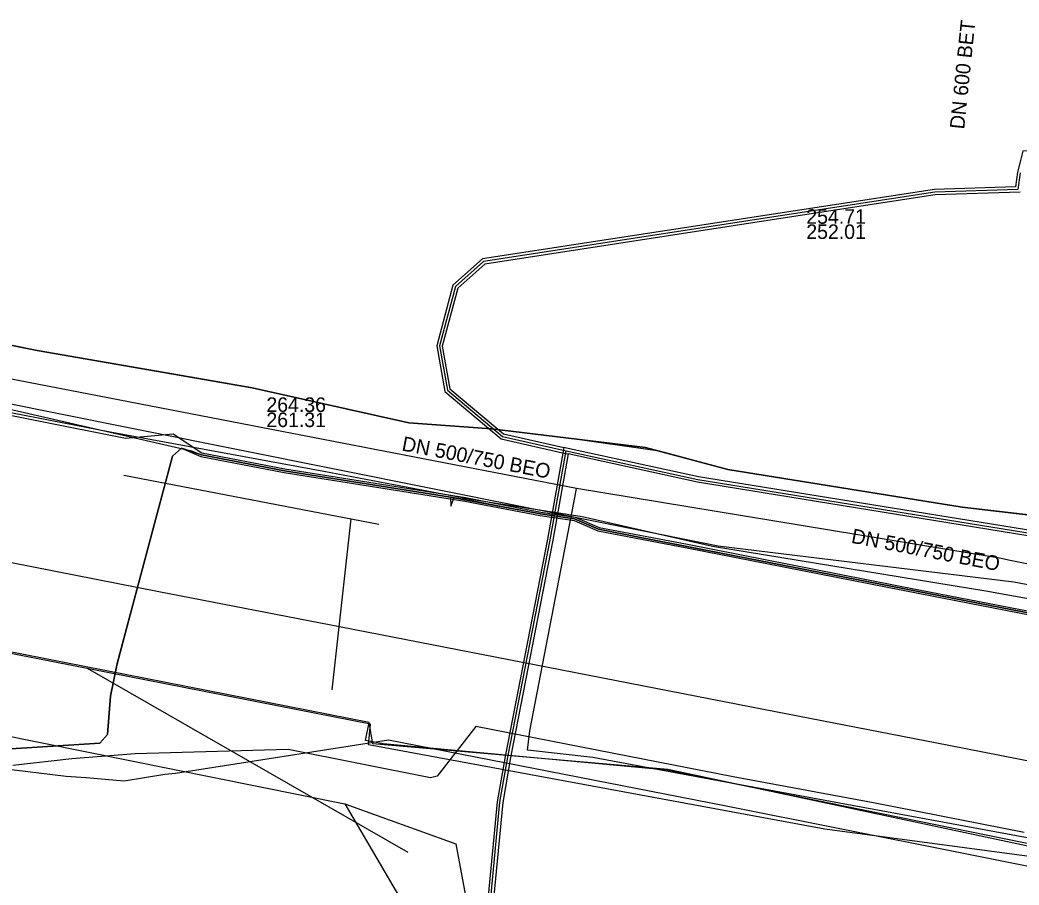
# Model space of a CAD drawing. Extents: x -599951 to -598963, y -1164095 to -1162939.
# Drawn here: x -599878 to -599823.1, y -1163059.7 to -1163012.2 of the extents above; entities that cross this region are included whole.
import ezdxf

# ---------------------------------------------------------------- set-up
doc = ezdxf.new("R2010")
doc.units = 0
for name, color, linetype in [('Vrstva 12', 7, 'Continuous'), ('Vrstva 19', 7, 'Continuous'), ('Vrstva 20', 7, 'Continuous'), ('Vrstva 42', 7, 'Continuous'), ('Vrstva 44', 7, 'Continuous'), ('Vrstva 50', 7, 'Continuous'), ('Vrstva 55', 7, 'Continuous'), ('Vrstva 58', 7, 'Continuous'), ('Vrstva 9', 7, 'Continuous')]:
    doc.layers.add(name, color=color, linetype=linetype)

msp = doc.modelspace()

# ---------------------------------------------------------------- linework, layer by layer
at = {"layer": 'Vrstva 12'}
for p, q in [((-599847.38, -1163037.95), (-599925.54, -1163022.8)), ((-599824.16, -1163041.78), (-599847.38, -1163037.95)), ((-599823.57, -1163041.9), (-599824.16, -1163041.78)), ((-599821.8, -1163042.25), (-599823.57, -1163041.9)), ((-599882.67, -1163050.72), (-599860.12, -1163055.28))]:
    msp.add_line(p, q, dxfattribs=at)
for points in [[(-599846.49, -1163052.73), (-599850.07, -1163052.32), (-599849.95, -1163051.27), (-599847.53, -1163038.73), (-599847.38, -1163037.95)], [(-599808.4, -1163075.41), (-599806.05, -1163063.47), (-599805.96, -1163062.96), (-599805.85, -1163062.25), (-599805.95, -1163061.63), (-599806.18, -1163061.15), (-599806.36, -1163060.78), (-599806.57, -1163060.51), (-599807.02, -1163060.09), (-599808.54, -1163059.75), (-599841.96, -1163053.57), (-599846.49, -1163052.73)], [(-599860.12, -1163055.28), (-599854.02, -1163057.48), (-599852.65, -1163064.87), (-599821.22, -1163071.4), (-599813.284, -1163073.958)], [(-599860.12, -1163055.28), (-599856.6, -1163061.29), (-599853.92, -1163067.61), (-599829.07, -1163071.62), (-599820.67, -1163074.02), (-599813.582, -1163075.481)]]:
    msp.add_lwpolyline(points, dxfattribs=at)
at = {"layer": 'Vrstva 19'}
for points in [[(-599875.409, -1163053.774), (-599879.03, -1163053.341), (-599951.125, -1163042.261)], [(-599741.561, -1163083.741), (-599749.337, -1163082.368), (-599759.986, -1163080.568), (-599773.585, -1163078.162), (-599785.969, -1163075.634), (-599789.812, -1163076.062), (-599794.62, -1163074.71), (-599796.63, -1163073), (-599800.62, -1163069), (-599804.87, -1163064.7), (-599807.8, -1163061.67), (-599826.41, -1163057.95), (-599839.25, -1163055.38), (-599857.71, -1163051.77), (-599869.416, -1163053.613), (-599869.995, -1163053.663), (-599872.225, -1163054.024), (-599874.316, -1163053.849), (-599875.409, -1163053.774)]]:
    msp.add_lwpolyline(points, dxfattribs=at)
at = {"layer": 'Vrstva 20'}
msp.add_lwpolyline([(-599883.05, -1163052.54), (-599873.56, -1163051.94), (-599873.14, -1163051.47), (-599872.98, -1163049.36), (-599872.6, -1163047.57), (-599869.57, -1163036.17), (-599869.08, -1163035.73), (-599867.99, -1163036.09), (-599863.42, -1163036.97), (-599853.5, -1163038.54), (-599849.37, -1163039.34), (-599847.49, -1163039.61), (-599846.18, -1163040.18), (-599841.31, -1163041.11), (-599828.6, -1163043.61), (-599815.43, -1163046.17), (-599809.1, -1163047.15), (-599803.22, -1163048.59), (-599792.42, -1163050.98), (-599783.94, -1163051.78), (-599774.84, -1163053.7), (-599762.66, -1163055.93), (-599749, -1163058.61), (-599740.93, -1163058.73)], dxfattribs=at)
at = {"layer": 'Vrstva 42'}
for p, q in [((-599895.104, -1163026.704), (-599877.002, -1163030.363)), ((-599895.104, -1163026.704), (-599877.002, -1163030.363)), ((-599877.002, -1163030.363), (-599865.209, -1163032.412)), ((-599877.002, -1163030.363), (-599865.209, -1163032.412)), ((-599865.209, -1163032.412), (-599856.59, -1163034.344)), ((-599865.209, -1163032.412), (-599856.59, -1163034.344)), ((-599856.59, -1163034.344), (-599852.059, -1163034.673)), ((-599856.59, -1163034.344), (-599852.059, -1163034.673)), ((-599852.059, -1163034.673), (-599843.593, -1163035.7)), ((-599852.059, -1163034.673), (-599843.593, -1163035.7)), ((-599843.593, -1163035.7), (-599839.077, -1163036.896)), ((-599843.593, -1163035.7), (-599839.077, -1163036.896)), ((-599839.077, -1163036.896), (-599826.206, -1163038.978)), ((-599839.077, -1163036.896), (-599826.206, -1163038.978)), ((-599826.206, -1163038.978), (-599807.734, -1163041.119)), ((-599826.206, -1163038.978), (-599807.734, -1163041.119))]:
    msp.add_line(p, q, dxfattribs=at)
for points in [[(-599815.518, -1163019.48), (-599820.791, -1163019.23), (-599821.01, -1163019.37), (-599822.87, -1163019.4), (-599823.02, -1163019.991), (-599823.159, -1163020.568), (-599823.271, -1163021.364), (-599827.714, -1163021.51), (-599835.493, -1163022.702), (-599852.557, -1163025.328), (-599854.173, -1163026.768), (-599855.063, -1163030.103), (-599854.618, -1163032.62), (-599851.529, -1163035.218), (-599847.993, -1163036.016), (-599847.84, -1163036.05), (-599848.693, -1163040.788), (-599851.012, -1163052.737), (-599851.441, -1163055.21), (-599851.947, -1163060.521), (-599893.107, -1163090.941)], [(-599815.518, -1163019.48), (-599820.791, -1163019.23), (-599821.01, -1163019.37), (-599822.87, -1163019.4), (-599823.02, -1163019.991), (-599823.159, -1163020.568), (-599823.271, -1163021.364), (-599827.714, -1163021.51), (-599835.493, -1163022.702), (-599852.557, -1163025.328), (-599854.173, -1163026.768), (-599855.063, -1163030.103), (-599854.618, -1163032.62), (-599851.529, -1163035.218), (-599847.993, -1163036.016), (-599847.84, -1163036.05), (-599848.693, -1163040.788), (-599851.012, -1163052.737), (-599851.441, -1163055.21), (-599851.947, -1163060.521), (-599893.107, -1163090.941)], [(-599823.02, -1163019.991), (-599823.159, -1163020.568), (-599823.271, -1163021.364), (-599827.714, -1163021.51), (-599835.493, -1163022.702), (-599852.557, -1163025.328), (-599854.173, -1163026.768), (-599855.063, -1163030.103), (-599854.618, -1163032.62), (-599851.529, -1163035.218), (-599847.993, -1163036.016), (-599847.84, -1163036.05), (-599848.693, -1163040.788), (-599851.012, -1163052.737), (-599851.441, -1163055.21), (-599851.947, -1163060.521), (-599893.107, -1163090.941)], [(-599823.02, -1163019.991), (-599823.159, -1163020.568), (-599823.271, -1163021.364), (-599827.714, -1163021.51), (-599835.493, -1163022.702), (-599852.557, -1163025.328), (-599854.173, -1163026.768), (-599855.063, -1163030.103), (-599854.618, -1163032.62), (-599851.529, -1163035.218), (-599847.993, -1163036.016), (-599847.84, -1163036.05), (-599848.693, -1163040.788), (-599851.012, -1163052.737), (-599851.441, -1163055.21), (-599851.947, -1163060.521), (-599893.107, -1163090.941)], [(-599823.159, -1163020.568), (-599823.271, -1163021.364), (-599827.714, -1163021.51), (-599835.493, -1163022.702), (-599852.557, -1163025.328), (-599854.173, -1163026.768), (-599855.063, -1163030.103), (-599854.618, -1163032.62), (-599851.529, -1163035.218), (-599847.993, -1163036.016), (-599847.84, -1163036.05), (-599848.693, -1163040.788), (-599851.012, -1163052.737), (-599851.441, -1163055.21), (-599851.947, -1163060.521), (-599893.107, -1163090.941), (-599898.107, -1163096.736), (-599905.507, -1163118.786), (-599909.197, -1163130.516), (-599919.149, -1163160.781), (-599923.658, -1163172.169), (-599928.466, -1163188.373), (-599951.125, -1163247.074)], [(-599823.159, -1163020.568), (-599823.271, -1163021.364), (-599827.714, -1163021.51), (-599835.493, -1163022.702), (-599852.557, -1163025.328), (-599854.173, -1163026.768), (-599855.063, -1163030.103), (-599854.618, -1163032.62), (-599851.529, -1163035.218), (-599847.993, -1163036.016), (-599847.84, -1163036.05), (-599848.693, -1163040.788), (-599851.012, -1163052.737), (-599851.441, -1163055.21), (-599851.947, -1163060.521), (-599893.107, -1163090.941), (-599898.107, -1163096.736), (-599905.507, -1163118.786), (-599909.197, -1163130.516), (-599919.149, -1163160.781), (-599923.658, -1163172.169), (-599928.466, -1163188.373), (-599951.125, -1163247.074)], [(-599823.01, -1163020.589), (-599823.14, -1163021.51)], [(-599823.009, -1163021.656), (-599827.686, -1163021.81), (-599835.447, -1163022.998), (-599852.423, -1163025.612), (-599853.907, -1163026.932), (-599854.757, -1163030.117), (-599854.342, -1163032.46), (-599851.391, -1163034.942), (-599848.08, -1163035.69), (-599848.987, -1163040.732), (-599851.308, -1163052.683), (-599851.739, -1163055.17), (-599852.233, -1163060.359), (-599893.313, -1163090.719)], [(-599823.009, -1163021.656), (-599827.686, -1163021.81), (-599835.447, -1163022.998), (-599852.423, -1163025.612), (-599853.907, -1163026.932), (-599854.757, -1163030.117), (-599854.342, -1163032.46), (-599851.391, -1163034.942), (-599848.08, -1163035.69), (-599848.987, -1163040.732), (-599851.308, -1163052.683), (-599851.739, -1163055.17), (-599852.233, -1163060.359), (-599893.313, -1163090.719)], [(-599823.14, -1163021.51), (-599827.7, -1163021.66), (-599835.47, -1163022.85), (-599852.49, -1163025.47), (-599854.04, -1163026.85), (-599854.91, -1163030.11), (-599854.48, -1163032.54), (-599851.46, -1163035.08), (-599847.96, -1163035.87)], [(-599736.94, -1163069.5), (-599747.67, -1163067.47), (-599759.18, -1163065.22), (-599771.56, -1163062.81), (-599782.31, -1163060.73), (-599794.22, -1163058.42), (-599806.06, -1163056.09), (-599817.5, -1163053.92), (-599826.93, -1163052.08), (-599837.11, -1163050.1), (-599848.95, -1163047.79), (-599860.32, -1163045.57), (-599870.33, -1163043.62), (-599881.88, -1163041.35), (-599892.48, -1163039.26), (-599902.25, -1163037.36), (-599911.67, -1163035.55), (-599921.63, -1163033.57), (-599932.53, -1163031.46), (-599941.74, -1163029.67), (-599951.125, -1163027.795)], [(-599742.215, -1163055.552), (-599755.449, -1163053.841), (-599771.375, -1163051.364), (-599782.13, -1163047.795), (-599795.02, -1163044.953), (-599808.565, -1163042.372), (-599820.407, -1163040.592), (-599840.692, -1163037.303), (-599847.928, -1163035.723), (-599848.08, -1163035.69), (-599848.987, -1163040.732), (-599851.308, -1163052.683), (-599851.739, -1163055.17), (-599852.233, -1163060.359), (-599893.313, -1163090.719), (-599898.373, -1163096.584), (-599905.793, -1163118.694), (-599909.483, -1163130.424), (-599919.431, -1163160.679), (-599923.942, -1163172.071), (-599928.754, -1163188.287), (-599951.125, -1163246.248)], [(-599742.215, -1163055.552), (-599755.449, -1163053.841), (-599771.375, -1163051.364), (-599782.13, -1163047.795), (-599795.02, -1163044.953), (-599808.565, -1163042.372), (-599820.407, -1163040.592), (-599840.692, -1163037.303), (-599847.928, -1163035.723), (-599848.08, -1163035.69), (-599848.987, -1163040.732), (-599851.308, -1163052.683), (-599851.739, -1163055.17), (-599852.233, -1163060.359), (-599893.313, -1163090.719), (-599898.373, -1163096.584), (-599905.793, -1163118.694), (-599909.483, -1163130.424), (-599919.431, -1163160.679), (-599923.942, -1163172.071), (-599928.754, -1163188.287), (-599951.125, -1163246.248)], [(-599742.265, -1163055.848), (-599755.491, -1163054.139), (-599771.445, -1163051.656), (-599782.21, -1163048.085), (-599795.08, -1163045.247), (-599808.615, -1163042.668), (-599820.453, -1163040.888), (-599840.748, -1163037.597), (-599847.84, -1163036.05), (-599848.693, -1163040.788), (-599851.012, -1163052.737), (-599851.441, -1163055.21), (-599851.947, -1163060.521), (-599893.107, -1163090.941), (-599898.107, -1163096.736), (-599905.507, -1163118.786), (-599909.197, -1163130.516), (-599919.149, -1163160.781), (-599923.658, -1163172.169), (-599928.466, -1163188.373), (-599951.125, -1163247.074)], [(-599742.265, -1163055.848), (-599755.491, -1163054.139), (-599771.445, -1163051.656), (-599782.21, -1163048.085), (-599795.08, -1163045.247), (-599808.615, -1163042.668), (-599820.453, -1163040.888), (-599840.748, -1163037.597), (-599847.84, -1163036.05), (-599848.693, -1163040.788), (-599851.012, -1163052.737), (-599851.441, -1163055.21), (-599851.947, -1163060.521), (-599893.107, -1163090.941), (-599898.107, -1163096.736), (-599905.507, -1163118.786), (-599909.197, -1163130.516), (-599919.149, -1163160.781), (-599923.658, -1163172.169), (-599928.466, -1163188.373), (-599951.125, -1163247.074)], [(-599928.61, -1163188.33), (-599923.8, -1163172.12), (-599919.29, -1163160.73), (-599909.34, -1163130.47), (-599905.65, -1163118.74), (-599898.24, -1163096.66), (-599893.21, -1163090.83), (-599852.09, -1163060.44), (-599851.59, -1163055.19), (-599851.16, -1163052.71), (-599848.84, -1163040.76), (-599847.96, -1163035.87)], [(-599847.96, -1163035.87), (-599840.72, -1163037.45), (-599820.43, -1163040.74), (-599808.59, -1163042.52), (-599795.05, -1163045.1), (-599782.17, -1163047.94), (-599771.41, -1163051.51), (-599755.47, -1163053.99), (-599742.24, -1163055.7), (-599730.83, -1163058.1), (-599723.97, -1163059.15), (-599715.25, -1163060.7), (-599698.74, -1163063.9), (-599666.16, -1163068.57), (-599655.17, -1163067.91), (-599647.96, -1163067.11), (-599641.24, -1163065.92), (-599633.17, -1163063.6), (-599622.92, -1163059.72), (-599616.64, -1163055.22), (-599609.94, -1163050.49)], [(-599822.79, -1163056.85), (-599830.99, -1163055.24), (-599838.79, -1163053.79), (-599852.91, -1163051.03), (-599855.04, -1163053.76), (-599855.4, -1163053.85), (-599863.22, -1163052.29), (-599871.63, -1163052.53), (-599875.11, -1163052.81), (-599878.35, -1163053.17)]]:
    msp.add_lwpolyline(points, dxfattribs=at)
at = {"layer": 'Vrstva 44'}
msp.add_lwpolyline([(-599951.125, -1163018.319), (-599947.551, -1163019.333), (-599942.738, -1163020.646), (-599932.806, -1163022.793), (-599910.515, -1163027.389), (-599898.233, -1163029.739), (-599885.727, -1163032.363), (-599873.009, -1163034.84), (-599861.264, -1163036.995), (-599853.19, -1163038.533), (-599847.084, -1163039.492), (-599839.909, -1163041.111), (-599824.895, -1163043.577), (-599814.349, -1163045.484), (-599801.363, -1163047.973), (-599790.063, -1163050.107), (-599778.01, -1163052.554), (-599760.155, -1163055.725), (-599748.035, -1163058.372), (-599724.432, -1163062.801)], dxfattribs=at)
at = {"layer": 'Vrstva 50'}
msp.add_lwpolyline([(-599815.43, -1163046.17), (-599843.958, -1163040.613), (-599846.18, -1163040.18), (-599847.49, -1163039.61), (-599849.37, -1163039.34), (-599854.299, -1163038.414), (-599863.42, -1163036.97), (-599867.99, -1163036.09), (-599869.08, -1163035.73), (-599869.57, -1163036.17), (-599872.613, -1163047.558), (-599872.98, -1163049.36), (-599873.14, -1163051.47), (-599873.56, -1163051.94), (-599883.05, -1163052.54)], dxfattribs=at)
at = {"layer": 'Vrstva 55'}
for points in [[(-599883.95, -1163032.34), (-599868.54, -1163035.88), (-599867.99, -1163036.09), (-599863.42, -1163036.97), (-599854.299, -1163038.414), (-599854.28, -1163038.91), (-599854.101, -1163038.446), (-599853.5, -1163038.54), (-599849.37, -1163039.34), (-599847.49, -1163039.61), (-599846.18, -1163040.18), (-599815.43, -1163046.17)], [(-599664.02, -1163109.18), (-599663.75, -1163108.82), (-599661.75, -1163109.07), (-599658.99, -1163095.65), (-599655.61, -1163093.65), (-599653.6, -1163094.02), (-599652.97, -1163091.01), (-599676.92, -1163086.63), (-599680.55, -1163086.75), (-599712.65, -1163080.11), (-599750.51, -1163072.96), (-599770.19, -1163068.95), (-599811.009, -1163059.716), (-599833.75, -1163056.67), (-599858.82, -1163052.03), (-599858.7, -1163050.9), (-599897.68, -1163043.25), (-599927.27, -1163037.74), (-599948.58, -1163035.1), (-599951.125, -1163035.045)], [(-599664.02, -1163109.18), (-599663.73, -1163108.63), (-599661.59, -1163109.02), (-599659.06, -1163095.58), (-599655.95, -1163093.64), (-599653.8, -1163094.03), (-599652.83, -1163091.3), (-599676.97, -1163086.63), (-599680.67, -1163086.82), (-599708.89, -1163080.98), (-599759.5, -1163071.06), (-599842.375, -1163053.387), (-599858.58, -1163051.98), (-599858.78, -1163050.81), (-599893.42, -1163044), (-599928.85, -1163037.58), (-599938.78, -1163036.41), (-599941.11, -1163043.03), (-599943.478, -1163048.564)], [(-599711.23, -1163080.4), (-599759.11, -1163071.25), (-599811.043, -1163059.819), (-599842.409, -1163053.422), (-599858, -1163051.98), (-599858.97, -1163051.79), (-599858.78, -1163050.81), (-599893.42, -1163044), (-599896.93, -1163051.01), (-599905.105, -1163053.383), (-599913.454, -1163056.211), (-599913.92, -1163056.19), (-599917.22, -1163057.25), (-599922.701, -1163059.24), (-599920.87, -1163063.66), (-599928.88, -1163069.16), (-599943.308, -1163079.607), (-599947.254, -1163081.556), (-599951.125, -1163083.176)], [(-599874.27, -1163047.83), (-599856.66, -1163057.93)]]:
    msp.add_lwpolyline(points, dxfattribs=at)
at = {"layer": 'Vrstva 58'}
for points in [[(-599951.125, -1163017.951), (-599942.396, -1163020.445), (-599928.216, -1163023.175), (-599909.436, -1163026.875), (-599898.216, -1163029.295), (-599876.466, -1163033.695), (-599839.596, -1163041.095), (-599823.356, -1163043.075), (-599809.226, -1163045.765), (-599771.136, -1163052.985), (-599752.946, -1163056.655), (-599739.506, -1163059.075)], [(-599951.125, -1163017.951), (-599942.396, -1163020.445), (-599928.216, -1163023.175), (-599909.436, -1163026.875), (-599898.216, -1163029.295), (-599876.466, -1163033.695), (-599839.596, -1163041.095), (-599823.356, -1163043.075), (-599809.226, -1163045.765), (-599771.136, -1163052.985), (-599752.946, -1163056.655), (-599739.506, -1163059.075)], [(-599951.125, -1163018.43), (-599950.947, -1163018.473), (-599944.048, -1163020.863), (-599872.152, -1163035.186), (-599869.54, -1163034.95)], [(-599807.734, -1163041.119), (-599826.206, -1163038.978), (-599839.077, -1163036.896), (-599843.593, -1163035.7), (-599852.059, -1163034.673), (-599856.59, -1163034.344), (-599865.209, -1163032.412), (-599877.002, -1163030.363), (-599895.104, -1163026.704)], [(-599895.104, -1163026.704), (-599877.002, -1163030.363), (-599865.209, -1163032.412), (-599856.59, -1163034.344), (-599852.059, -1163034.673), (-599843.593, -1163035.7), (-599839.077, -1163036.896), (-599826.206, -1163038.978), (-599807.734, -1163041.119), (-599798.148, -1163043.163), (-599783.799, -1163046.138), (-599778.116, -1163047.934), (-599767.984, -1163049.822), (-599757.25, -1163051.301), (-599755.861, -1163052.095), (-599756.19, -1163053.12), (-599756.43, -1163053.89), (-599756.84, -1163055.76), (-599757.116, -1163057.018), (-599762.66, -1163055.93)], [(-599895.104, -1163026.704), (-599877.002, -1163030.363), (-599865.209, -1163032.412), (-599856.59, -1163034.344), (-599852.059, -1163034.673), (-599843.593, -1163035.7), (-599839.077, -1163036.896), (-599826.206, -1163038.978), (-599807.734, -1163041.119), (-599798.148, -1163043.163), (-599783.799, -1163046.138), (-599778.116, -1163047.934), (-599767.984, -1163049.822), (-599757.25, -1163051.301), (-599755.861, -1163052.095), (-599756.19, -1163053.12), (-599756.43, -1163053.89), (-599756.84, -1163055.76), (-599757.116, -1163057.018), (-599762.66, -1163055.93)], [(-599807.734, -1163041.119), (-599826.206, -1163038.978), (-599839.077, -1163036.896), (-599843.593, -1163035.7), (-599852.059, -1163034.673), (-599856.59, -1163034.344), (-599865.209, -1163032.412), (-599877.002, -1163030.363), (-599895.104, -1163026.704)], [(-599807.734, -1163041.119), (-599826.206, -1163038.978), (-599839.077, -1163036.896), (-599843.593, -1163035.7), (-599852.059, -1163034.673), (-599856.59, -1163034.344), (-599865.209, -1163032.412), (-599877.002, -1163030.363), (-599895.104, -1163026.704)], [(-599895.104, -1163026.704), (-599877.002, -1163030.363), (-599865.209, -1163032.412), (-599856.59, -1163034.344), (-599852.059, -1163034.673), (-599843.593, -1163035.7), (-599839.077, -1163036.896), (-599826.206, -1163038.978), (-599807.734, -1163041.119), (-599798.148, -1163043.163), (-599783.799, -1163046.138), (-599778.116, -1163047.934), (-599767.984, -1163049.822), (-599757.25, -1163051.301), (-599755.861, -1163052.095), (-599756.19, -1163053.12), (-599756.43, -1163053.89), (-599756.84, -1163055.76), (-599757.116, -1163057.018), (-599762.66, -1163055.93)], [(-599807.734, -1163041.119), (-599826.206, -1163038.978), (-599839.077, -1163036.896), (-599842.831, -1163035.902), (-599847.972, -1163035.169), (-599852.059, -1163034.673), (-599856.59, -1163034.344), (-599865.209, -1163032.412), (-599867.711, -1163031.977), (-599877.002, -1163030.363), (-599882.297, -1163029.293)], [(-599869.54, -1163034.95), (-599867.965, -1163035.993), (-599863.403, -1163036.871), (-599853.483, -1163038.441), (-599849.353, -1163039.241), (-599847.462, -1163039.513), (-599846.15, -1163040.084), (-599841.291, -1163041.012), (-599828.581, -1163043.512), (-599815.413, -1163046.071), (-599809.08, -1163047.052), (-599803.197, -1163048.493), (-599792.404, -1163050.881), (-599783.925, -1163051.681), (-599774.821, -1163053.602), (-599762.641, -1163055.832), (-599748.99, -1163058.51), (-599740.918, -1163058.63)], [(-599883.05, -1163052.54), (-599873.56, -1163051.94), (-599873.14, -1163051.47), (-599872.98, -1163049.36), (-599872.613, -1163047.558), (-599869.57, -1163036.17), (-599869.08, -1163035.73), (-599867.99, -1163036.09), (-599863.42, -1163036.97), (-599854.299, -1163038.414), (-599849.37, -1163039.34), (-599847.49, -1163039.61), (-599846.18, -1163040.18), (-599843.958, -1163040.613), (-599815.43, -1163046.17)], [(-599762.66, -1163055.93), (-599772.176, -1163054.188), (-599774.84, -1163053.7), (-599783.94, -1163051.78), (-599792.42, -1163050.98), (-599803.22, -1163048.59), (-599809.1, -1163047.15), (-599809.988, -1163047.015), (-599815.43, -1163046.17), (-599843.958, -1163040.613), (-599846.18, -1163040.18), (-599847.49, -1163039.61), (-599849.37, -1163039.34), (-599854.299, -1163038.414), (-599863.42, -1163036.97), (-599867.99, -1163036.09), (-599869.08, -1163035.73), (-599869.57, -1163036.17), (-599872.613, -1163047.558), (-599872.98, -1163049.36), (-599873.14, -1163051.47), (-599873.56, -1163051.94), (-599883.05, -1163052.54)], [(-599762.66, -1163055.93), (-599772.176, -1163054.188), (-599774.84, -1163053.7), (-599783.94, -1163051.78), (-599792.42, -1163050.98), (-599803.22, -1163048.59), (-599809.1, -1163047.15), (-599809.988, -1163047.015), (-599815.43, -1163046.17), (-599843.958, -1163040.613), (-599846.18, -1163040.18), (-599847.49, -1163039.61), (-599849.37, -1163039.34), (-599854.299, -1163038.414), (-599863.42, -1163036.97), (-599867.99, -1163036.09), (-599869.08, -1163035.73), (-599869.57, -1163036.17), (-599872.613, -1163047.558), (-599872.98, -1163049.36), (-599873.14, -1163051.47), (-599873.56, -1163051.94), (-599883.05, -1163052.54)], [(-599883.05, -1163052.54), (-599873.56, -1163051.94), (-599873.14, -1163051.47), (-599872.98, -1163049.36), (-599872.613, -1163047.558), (-599869.57, -1163036.17), (-599869.08, -1163035.73), (-599867.99, -1163036.09), (-599863.42, -1163036.97), (-599854.299, -1163038.414), (-599849.37, -1163039.34), (-599847.49, -1163039.61), (-599846.18, -1163040.18), (-599843.958, -1163040.613), (-599815.43, -1163046.17)], [(-599883.05, -1163052.54), (-599873.56, -1163051.94), (-599873.14, -1163051.47), (-599872.98, -1163049.36), (-599872.613, -1163047.558), (-599869.57, -1163036.17), (-599869.08, -1163035.73), (-599867.99, -1163036.09), (-599863.42, -1163036.97), (-599854.299, -1163038.414), (-599849.37, -1163039.34), (-599847.49, -1163039.61), (-599846.18, -1163040.18), (-599843.958, -1163040.613), (-599815.43, -1163046.17)], [(-599762.66, -1163055.93), (-599772.176, -1163054.188), (-599774.84, -1163053.7), (-599783.94, -1163051.78), (-599792.42, -1163050.98), (-599803.22, -1163048.59), (-599809.1, -1163047.15), (-599809.988, -1163047.015), (-599815.43, -1163046.17), (-599843.958, -1163040.613), (-599846.18, -1163040.18), (-599847.49, -1163039.61), (-599849.37, -1163039.34), (-599854.299, -1163038.414), (-599863.42, -1163036.97), (-599867.99, -1163036.09), (-599869.08, -1163035.73), (-599869.57, -1163036.17), (-599872.613, -1163047.558), (-599872.98, -1163049.36), (-599873.14, -1163051.47), (-599873.56, -1163051.94), (-599883.05, -1163052.54)], [(-599883.05, -1163052.54), (-599873.56, -1163051.94), (-599873.14, -1163051.47), (-599872.98, -1163049.36), (-599872.6, -1163047.57), (-599869.57, -1163036.17), (-599869.08, -1163035.73), (-599868.015, -1163036.187), (-599863.437, -1163037.069), (-599853.517, -1163038.639), (-599849.387, -1163039.439), (-599847.518, -1163039.707), (-599846.21, -1163040.276), (-599841.329, -1163041.208), (-599828.619, -1163043.708), (-599815.447, -1163046.269), (-599809.12, -1163047.248), (-599803.243, -1163048.687), (-599792.436, -1163051.079), (-599783.955, -1163051.879)], [(-599883.05, -1163052.54), (-599873.56, -1163051.94), (-599873.14, -1163051.47), (-599872.98, -1163049.36), (-599872.6, -1163047.57), (-599869.57, -1163036.17), (-599869.08, -1163035.73), (-599868.015, -1163036.187), (-599863.437, -1163037.069), (-599853.517, -1163038.639), (-599849.387, -1163039.439), (-599847.518, -1163039.707), (-599846.21, -1163040.276), (-599841.329, -1163041.208), (-599828.619, -1163043.708), (-599815.447, -1163046.269), (-599809.12, -1163047.248), (-599803.243, -1163048.687), (-599792.436, -1163051.079), (-599783.955, -1163051.879)]]:
    msp.add_lwpolyline(points, dxfattribs=at)
at = {"layer": 'Vrstva 9'}
for p, q in [((-599872.244, -1163037.215), (-599858.25, -1163039.91)), ((-599860.81, -1163049.01), (-599859.768, -1163039.613))]:
    msp.add_line(p, q, dxfattribs=at)

# ---------------------------------------------------------------- texts
at = {"layer": 'Vrstva 12'}
for s, rotation, p in [('DN 600 BET', 84.1112, (-599826.092, -1163018.227)), ('DN 500/750 BEO', 349.1407, (-599857.022, -1163035.854)), ('DN 500/750 BEO', 349.1016, (-599832.335, -1163040.926))]:
    msp.add_text(s, height=0.8, rotation=rotation, dxfattribs=at).set_placement(p)
for s, p in [('254.71', (-599834.764, -1163023.399)), ('252.01', (-599834.764, -1163024.231)), ('264.36', (-599864.421, -1163033.739)), ('261.31', (-599864.421, -1163034.571))]:
    msp.add_text(s, height=0.8, dxfattribs=at).set_placement(p)

doc.saveas('drawing.dxf')
